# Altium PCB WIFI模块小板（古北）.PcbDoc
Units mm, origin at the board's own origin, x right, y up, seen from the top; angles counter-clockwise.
Board outline 152.4 x 101.6 mm, 2 copper layers (Top Layer, Bottom Layer); 1 components, 4 nets, 26 pads, 0 vias.
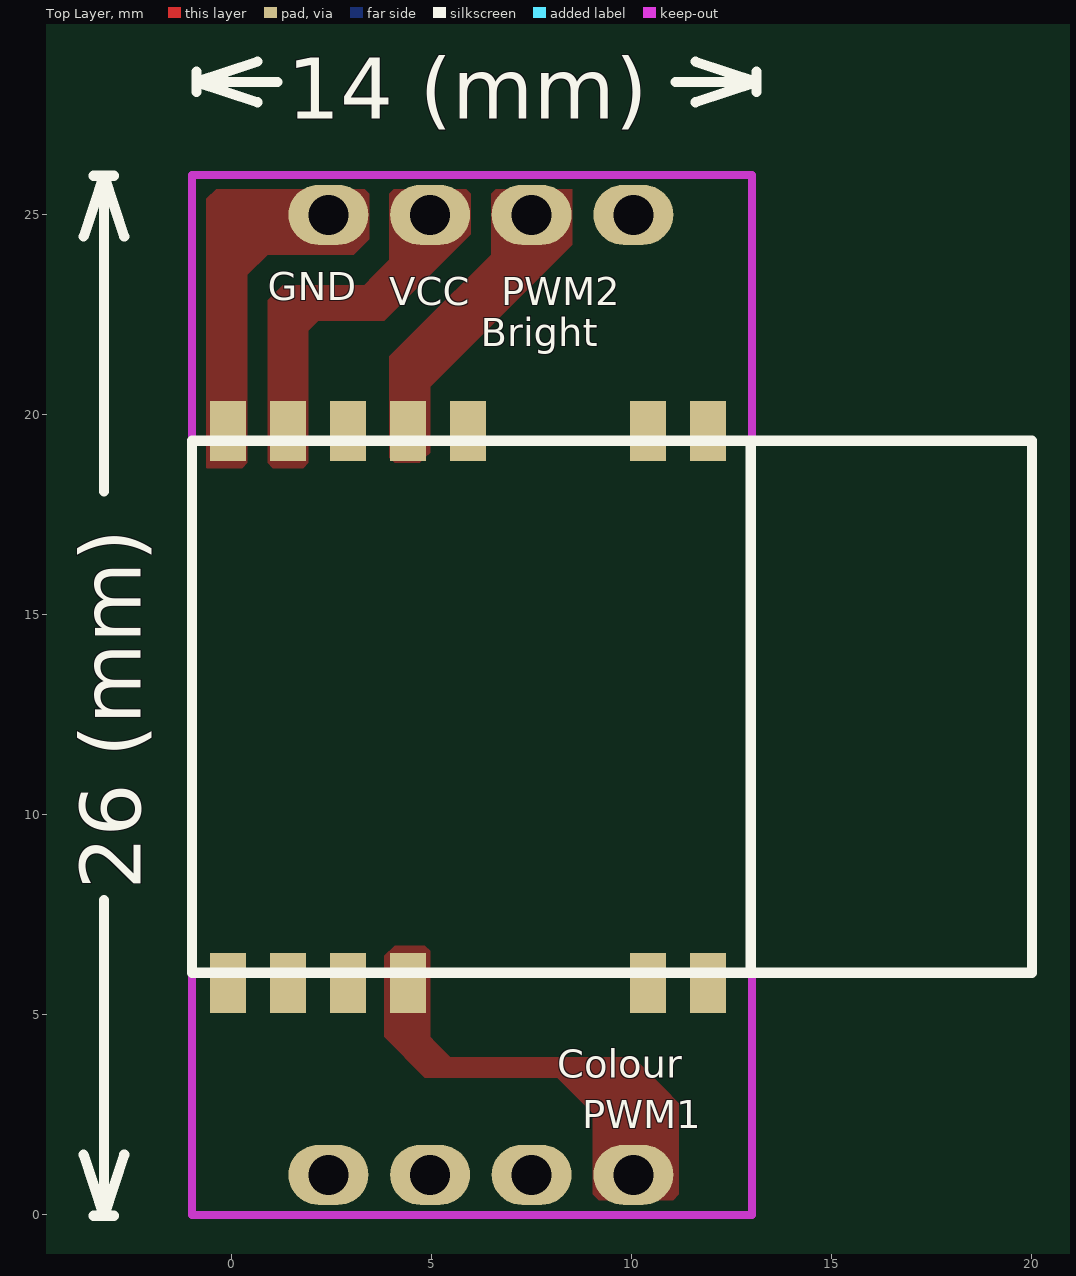
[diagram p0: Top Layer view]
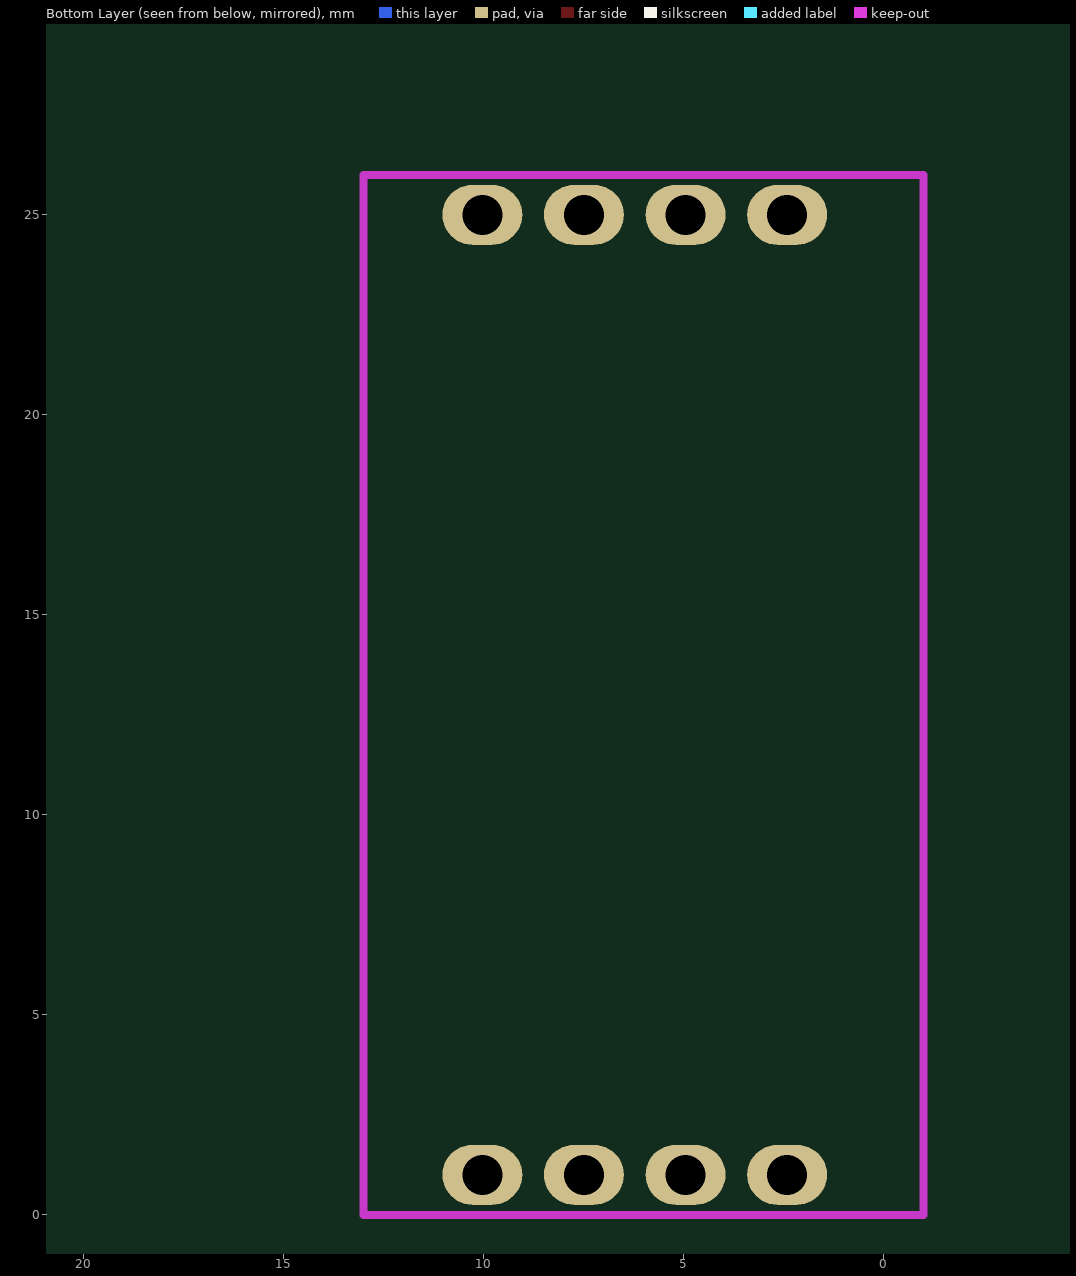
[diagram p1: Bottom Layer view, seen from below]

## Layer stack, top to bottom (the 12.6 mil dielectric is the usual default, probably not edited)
Top Solder: solder mask 0.0102, Solder Resist, Dk 3.5
Top Layer: signal copper 0.0356
Dielectric1: dielectric 0.32, FR-4, Dk 4.8
Bottom Layer: signal copper 0.0356
Bottom Solder: solder mask 0.0102, Solder Resist, Dk 3.5

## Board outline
-71.374,-52.467 81.026,-52.467 81.026,49.133 -71.374,49.133

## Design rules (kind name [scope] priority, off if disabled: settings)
Clearance [All] p1: gap=0.254 ignorepadtopadclearanceinfootprint=FALSE except(0: Arc-Hole Track-Hole SMDPad-Hole THPad-Hole Via-Hole Fill-Hole Poly-Hole Region-Hole Text-Hole)
PolygonConnect [All] p1: connectstyle=Direct reliefconductorwidth=0.254 reliefentries=4 polygonreliefangle="90 Angle" airgapwidth=0.254
RoutingVias [All] p1: holewidth=0.711 width=1.27 viastyle="Through Hole" minholewidth=0.711 minwidth=1.27 maxholewidth=0.711 maxwidth=1.27
SilkToSolderMaskClearance SilkscreenOverComponentPads [IsPad] p1: minsilkscreentomaskgap=0.254 clearancetoexposedcopper=TRUE
SolderMaskExpansion [All] p1: expansion=0.102
Width [All] p1: maxlimit=1 minlimit=0.254 preferedwidth=0.6
29 further rules are at their usual default settings.

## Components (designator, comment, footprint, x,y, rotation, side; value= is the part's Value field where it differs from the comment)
? "Comment" BL3335-P -1,12.7 r270 top

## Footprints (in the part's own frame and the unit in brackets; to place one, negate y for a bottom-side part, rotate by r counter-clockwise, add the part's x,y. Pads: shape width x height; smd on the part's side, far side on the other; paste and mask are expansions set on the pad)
BL3335-P [mm]
  rect 1.5x0.9 smd: 1(-6.9,12.9) 2(-6.9,11.4) 5(-6.9,6.9) "6 APWM"(-6.9,5.4) 7(-6.9,3.9) "8 VDD"(-6.9,2.4) "9 GND"(-6.9,0.9) 10(6.9,0.9) 11(6.9,2.4) 12(6.9,3.9) "13 DPWM"(6.9,5.4) 17(6.9,11.4) 18(6.9,12.9)
  rect 1.5x0.9 on Top Overlay: 3(-6.9,9.9) 4(-6.9,8.4) 14(6.9,6.9) 15(6.9,8.4) 16(6.9,9.9)
  silkscreen extent -6.65,0 6.65,21

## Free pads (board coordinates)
  oval 2x1.5 hole 1: 2(2.413,1) 2(2.413,25) 2(4.953,1) 2(4.953,25) 2(7.493,1) 2(7.493,25) 2(10.033,1) 2(10.033,25)

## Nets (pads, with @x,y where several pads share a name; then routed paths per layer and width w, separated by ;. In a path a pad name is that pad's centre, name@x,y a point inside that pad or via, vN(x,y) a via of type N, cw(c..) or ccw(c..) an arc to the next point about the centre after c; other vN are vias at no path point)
3: "?.8 VDD" pad.2@4.953,25
GND1: "?.9 GND" pad.2@2.413,25
NewNet14: "?.6 APWM" pad.2@7.493,25
NewNet15: "?.13 DPWM" pad.2@10.033,1
pads on no net: ?.1 ?.2 ?.3 ?.4 ?.5 ?.7 ?.10 ?.11 ?.12 ?.14 ?.15 ?.16 ?.17 ?.18

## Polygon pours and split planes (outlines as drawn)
GND1 on Top Layer "Top Layer-No Net" (solid, pour order 6): 2.413,24.511 2.413,24.003 3.048,24.003 3.429,24.384 3.429,25.527 3.175,25.781 1.905,25.781 -0.254,25.781 -0.762,25.273 -0.762,18.796 -0.635,18.669 0.254,18.669 0.381,18.796 0.381,23.495 0.889,24.003 2.413,24.003
3 on Top Layer "Top Layer-No Net" (solid, remove dead copper, pour order 4): 4.191,25.019 3.937,25.019 3.937,23.876 3.556,23.495 3.302,23.241 3.175,23.241 1.27,23.241 1.016,22.987 0.889,22.86 0.889,20.32 0.889,18.796 1.016,18.669 1.778,18.669 1.905,18.796 1.905,22.098 2.159,22.352 3.81,22.352 4.318,22.86 5.969,24.511 5.969,25.527 5.715,25.781 5.461,25.781 4.191,25.781 4.064,25.654 3.937,25.527 3.937,25.019
NewNet14 on Top Layer "Top Layer-No Net" (solid, remove dead copper, pour order 2): 7.493,24.511 7.493,24.13 8.382,24.13 8.509,24.257 8.509,25.654 8.382,25.781 6.731,25.781 6.477,25.527 6.477,24.003 4.699,22.225 3.937,21.463 3.937,19.812 3.937,18.923 4.064,18.796 4.699,18.796 4.826,18.923 4.953,19.05 4.953,19.304 4.953,20.701 8.382,24.13 7.493,24.13
NewNet15 on Top Layer "Top Layer-No Net" (solid, remove dead copper, pour order 0): 4.064,5.461 3.81,5.461 3.81,4.445 4.826,3.429 8.128,3.429 8.89,2.667 9.017,2.54 9.017,1.27 9.017,0.508 9.271,0.254 10.922,0.254 11.176,0.508 11.176,2.794 10.795,3.175 10.033,3.937 7.62,3.937 5.461,3.937 5.08,4.318 4.953,4.445 4.953,5.207 4.953,6.604 4.826,6.731 4.064,6.731 3.81,6.477 3.81,5.461

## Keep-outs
Keep-Out Layer:
  lines w0.2: -1,0 13,0 13,26 -1,26 -1,0

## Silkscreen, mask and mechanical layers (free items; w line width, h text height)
Top Overlay:
  lines w0.254: -3.708,1.502 -3.2,-0.022 ; -3.708,24.454 -3.2,25.978 ; -3.454,-0.022 -2.946,-0.022 ; -3.454,25.978 -2.946,25.978 ; -3.2,7.874 -3.2,-0.022 ; -3.2,18.082 -3.2,25.978 ; -2.692,1.502 -3.2,-0.022 ; -2.692,24.454 -3.2,25.978 ; -0.889,28.067 -0.889,28.575 ; 0.635,27.813 -0.889,28.321 ; 0.635,28.829 -0.889,28.321 ; 1.134,28.321 -0.889,28.321 ; 11.088,28.321 13.111,28.321 ; 11.587,27.813 13.111,28.321 ; 11.587,28.829 13.111,28.321 ; 13.111,28.067 13.111,28.575
  text "14 (mm)" at 1.388,27.407 h1.52
  text "GND" at 0.889,22.86 h0.7
  text "VCC" at 3.937,22.733 h0.7
  text "PWM2" at 6.731,22.733 h0.7
  text "Bright" at 6.223,21.717 h0.7
  text "26 (mm)" at -2.286,8.128 h1.52 r90
  text "Colour" at 8.128,3.429 h0.7
  text "PWM1" at 8.763,2.159 h0.7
